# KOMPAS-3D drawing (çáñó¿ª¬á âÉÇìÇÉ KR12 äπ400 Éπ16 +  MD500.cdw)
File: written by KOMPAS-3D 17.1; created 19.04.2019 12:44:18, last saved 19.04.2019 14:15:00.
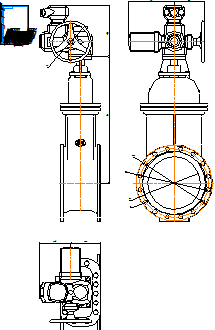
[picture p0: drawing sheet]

Sheet 1: A4, portrait

Title block, sheet 1: name: Задвижка ГРАНАР KR12 Ду400 Ру16 + / MD500; material: Внимание! Данный продукт является объектом авторского права ООО «Торговый Дом АДЛ». / Запрещается изменение, копирование, распространение / (в том числе путем копирования на другие сайты и ресурсы в Интернете) / или любое иное использование информации и объектов без предварительного / согласия правообладателя (ООО «Торговый Дом АДЛ»).; mass: 659,77; sheets: 1; organisation: ООО "Торговый дом АДЛ"; sheet format: A4; stored path: \\adlc.lan\data\АДЛ_ПКД\3D-модели\ADL production\Клиновые задвижки серии KR ГРАНАР\Клиновые задвижки KR12 с эл.приводами Смартгир\KOMPAS 2D\Задвижка ГРАНАР KR12 Ду400 Ру16 +  MD500.cdw

Views: Вид 1, Проекционный вид 3
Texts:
  user
Dimensions and other numbers on the sheet: 962; 391; 320; 241,19; 228,81; 1:1; 1; 659,77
